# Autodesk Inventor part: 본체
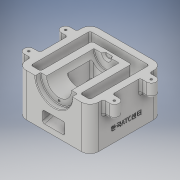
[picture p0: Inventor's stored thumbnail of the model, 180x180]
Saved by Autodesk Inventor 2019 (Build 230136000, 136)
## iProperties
Created: 2022-03
Part Number: 본체
Material: 일반
Document SubType Name: Modeling
Designer: LINE501-1
Density: 1 g/cm^3
Appearance: 기본값
Author: LINE501-1
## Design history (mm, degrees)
sketch "스케치2"
  geometry: L1 (55, 55)-(-55, 55); L2 (-55, 55)-(-55, -55); L3 (-55, -55)-(55, -55); L4 (55, -55)-(55, 55); L5 (55, 55)-(-55, -55); L6 (-55, 55)-(55, -55); L7 (45, 45)-(45, -45); L8 (45, -45)-(-45, -45); L9 (-45, -45)-(-45, 45); L10 (-45, 45)-(-30, 45); L11 (-30, -30)-(-30, 45); L12 (-30, -30)-(30, -30); L13 (30, -30)-(30, 45); L14 (30, 45)-(45, 45); L15 (65, -35)-(55, -35); L16 (65, -21)-(55, -21); A1 r 7 centre (65, -28) between (65, -35) and (65, -21); 1 further point
  constraints: 32 end point, 8 perpendicular, 6 point on line, 3 horizontal, 2 midpoint, 2 parallel, 2 point on circle, 2 tangent, 1 centre point, 1 vertical
  dimensions: "d13" = 110 distance of L3.end L2.end; "d14" = 110 distance of L2.end L1.end; "d15" = 10 distance between parallel lines of L14 L1; "d16" = 10 distance between parallel lines of L10 L1; "d17" = 25 distance between parallel lines of L4 L13; "d18" = 25 distance between parallel lines of L2 L11; "d19" = 14 diameter of A1; "d20" = 65 horizontal distance of A1.centre point (0, 0); "d21" = 27 distance from line of A1.centre L3
extrude "돌출2" new body sketch "스케치2" distance "d24" = 65; taper "d25" = 0 deg
sketch "스케치3"
  geometry: L1 (-45, -45)-(-45, 45); L2 (-45, 45)-(45, 45); L3 (45, 45)-(45, -45); L4 (45, -45)-(30, -45); L5 (30, -45)-(30, 33); L6 (30, 33)-(-30, 33); L7 (-30, 33)-(-30, -45); L8 (-45, -45)-(-30, -45); L9 (-55, -55)-(55, -55) reference; L10 (-55, 55)-(-55, -55) reference; L11 (55, 55)-(-55, 55) reference; L12 (55, -55)-(55, 55) reference; 1 further point
  constraints: 16 end point, 6 perpendicular, 1 parallel, 1 point on line, 1 vertical
  dimensions: "d26" = 10 distance between parallel lines of L9 L8; "d27" = 10 distance between parallel lines of L10 L1; "d28" = 25 distance between parallel lines of L10 L7; "d29" = 10 distance between parallel lines of L11 L2; "d30" = 10 distance between parallel lines of L12 L3; "d31" = 25 distance between parallel lines of L5 L12; "d32" = 22 distance between parallel lines of L11 L6
extrude "돌출3" cut sketch "스케치3" distance "d33" = 65; taper "d34" = 0 deg
sketch "스케치4"
  geometry: L1 (55, 55)-(-55, 55) reference; L2 (-65, 35)-(-55, 35); L3 (-65, 21)-(-55, 21); L4 (-55, 55)-(-55, -55) reference; A1 r 7 centre (-65, 28) between (-65, 35) and (-65, 21); 1 further point
  constraints: 4 end point, 2 horizontal, 2 point on circle, 2 point on line, 2 tangent, 1 centre point
  dimensions: "d36" = 14 diameter of A1; "d37" = 27 distance from line of A1.centre L1; "d38" = 65 horizontal distance of A1.centre point (0, 0)
extrude "돌출4" join sketch "스케치4" distance "d39" = 20; taper "d40" = 0 deg
sketch "스케치5"
  geometry: L1 (65, 55)-(37, 55); L2 (37, 55)-(37, 47); L3 (37, 47)-(46, 47); L4 (46, 47)-(46, -25); L5 (46, -25)-(57.5, -25); L6 (59.809, -29)-(65, -29); L7 (65, -29)-(65, 55); L8 (65, 45)-(65, -33) reference; L9 (57.5, -25)-(59.809, -29); 2 further points
  constraints: 16 end point, 2 perpendicular, 1 midpoint, 1 point on line, 1 vertical
  dimensions: "d44" = 8 distance between parallel lines of L3 L1; "d45" = 72 distance between parallel lines of L5 L3; "d46" = 4 distance between parallel lines of L6 L5; "d47" = 56 diameter of L2 L7; "d48" = 38 diameter of L4 L7; "d49" = 15 diameter of L5.end L7; "d50" = 120 deg angle of L9 L5
revolve "회전1" sketch "스케치5" stored, may be unused: angle "d51" = 90 deg
sketch "스케치7"
  geometry: L1 (8.381, 55)-(28.21, -19); L2 (35.627, 19)-(25.981, 55); L3 (8.381, 55)-(25.981, 55); L4 (5.885, 45)-(0, 45); L5 (28.21, -19)-(55.209, -19); L6 (55.209, -19)-(55.209, 19); L7 (55.209, 19)-(35.627, 19); L8 (0, -45)-(30, -45); L9 (30, -45)-(5.885, 45); L10 (0, -33)-(0, 45) reference; L11 (0, -45)-(0, 45)
  constraints: 20 end point, 2 horizontal, 2 parallel, 2 perpendicular, 1 vertical
  dimensions: "d56" = 36 distance between parallel lines of L7 L3; "d57" = 38 distance between parallel lines of L7 L5; "d61" = 17 distance between parallel lines of L2 L1; "d64" = 15 deg angle of L6 L1; "d87" = 30 distance of L8.start L8.end; "d88" = 75 deg angle of L9 L8; "d90" = 10 distance between parallel lines of L3 L4; "d91" = 55.20924 distance between parallel lines of L10 L6; "d92" = 5 distance between parallel lines of L9 L1
extrude "돌출5" cut sketch "스케치7" stored distance "d66" = 34; taper "d67" = 0 deg
sketch "스케치8"
  geometry: A1 r 7 centre (-65, 28) between (-65, 35) and (-65, 21) reference; A2 r 7 centre (65, 28) between (65, 21) and (65, 35) reference; A3 r 7 centre (65, -28) between (65, -35) and (65, -21) reference; A4 r 7 centre (-65, -28) between (-65, -21) and (-65, -35) reference; 1 further point
hole "구멍1" sketch "스케치8" at (65, 28), (65, -28), (-65, 28), (-65, -28) diameter "d70" = 3.242; stored, may be unused: countersink angle "d74" = 90 deg, drill point angle "d76" = 118 deg; dims "d71" = 9, "d72" = 18, "d73" = 2, "d75" = 11
sketch "스케치9" dims "d77" = 46
  geometry: 4 further points
  constraints: 2 coincident, 1 vertical alignment, 2 other
hole "구멍2" sketch "스케치9" at (0, -23) diameter "d78" = 3.242; stored, may be unused: countersink angle "d82" = 90 deg, drill point angle "d84" = 118 deg; dims "d79" = 9, "d80" = 18, "d81" = 2, "d83" = 11
fillet "모깎기1" dims "d85" = 13, "d86" = 1
extrude "돌출7" cut sketch "스케치7" stored distance "d93" = 80; taper "d94" = 0 deg
fillet "모깎기2" dims "d95" = 3
fillet "모깎기3" dims "d96" = 3
chamfer "모따기1" distance "d97" = 1; stored, may be unused: second distance "d98" = 2, angle "d99" = 45 deg
sketch "스케치10"
  geometry: L1 (-13, 65)-(-13, 0) reference; 2 further points
  constraints: 1 other
  dimensions: "d100" = 55 distance from line of point (42, 20) L1; "d101" = 20 distance of point (42, 20) point (42, 0)
feature "엠보싱1" sketch "스케치10" dims "d102" = 0.5, "d103" = 0
node "솔리드2"
pattern_linear "직사각형 패턴1" dims "d43" = 56
mirror "미러1"
